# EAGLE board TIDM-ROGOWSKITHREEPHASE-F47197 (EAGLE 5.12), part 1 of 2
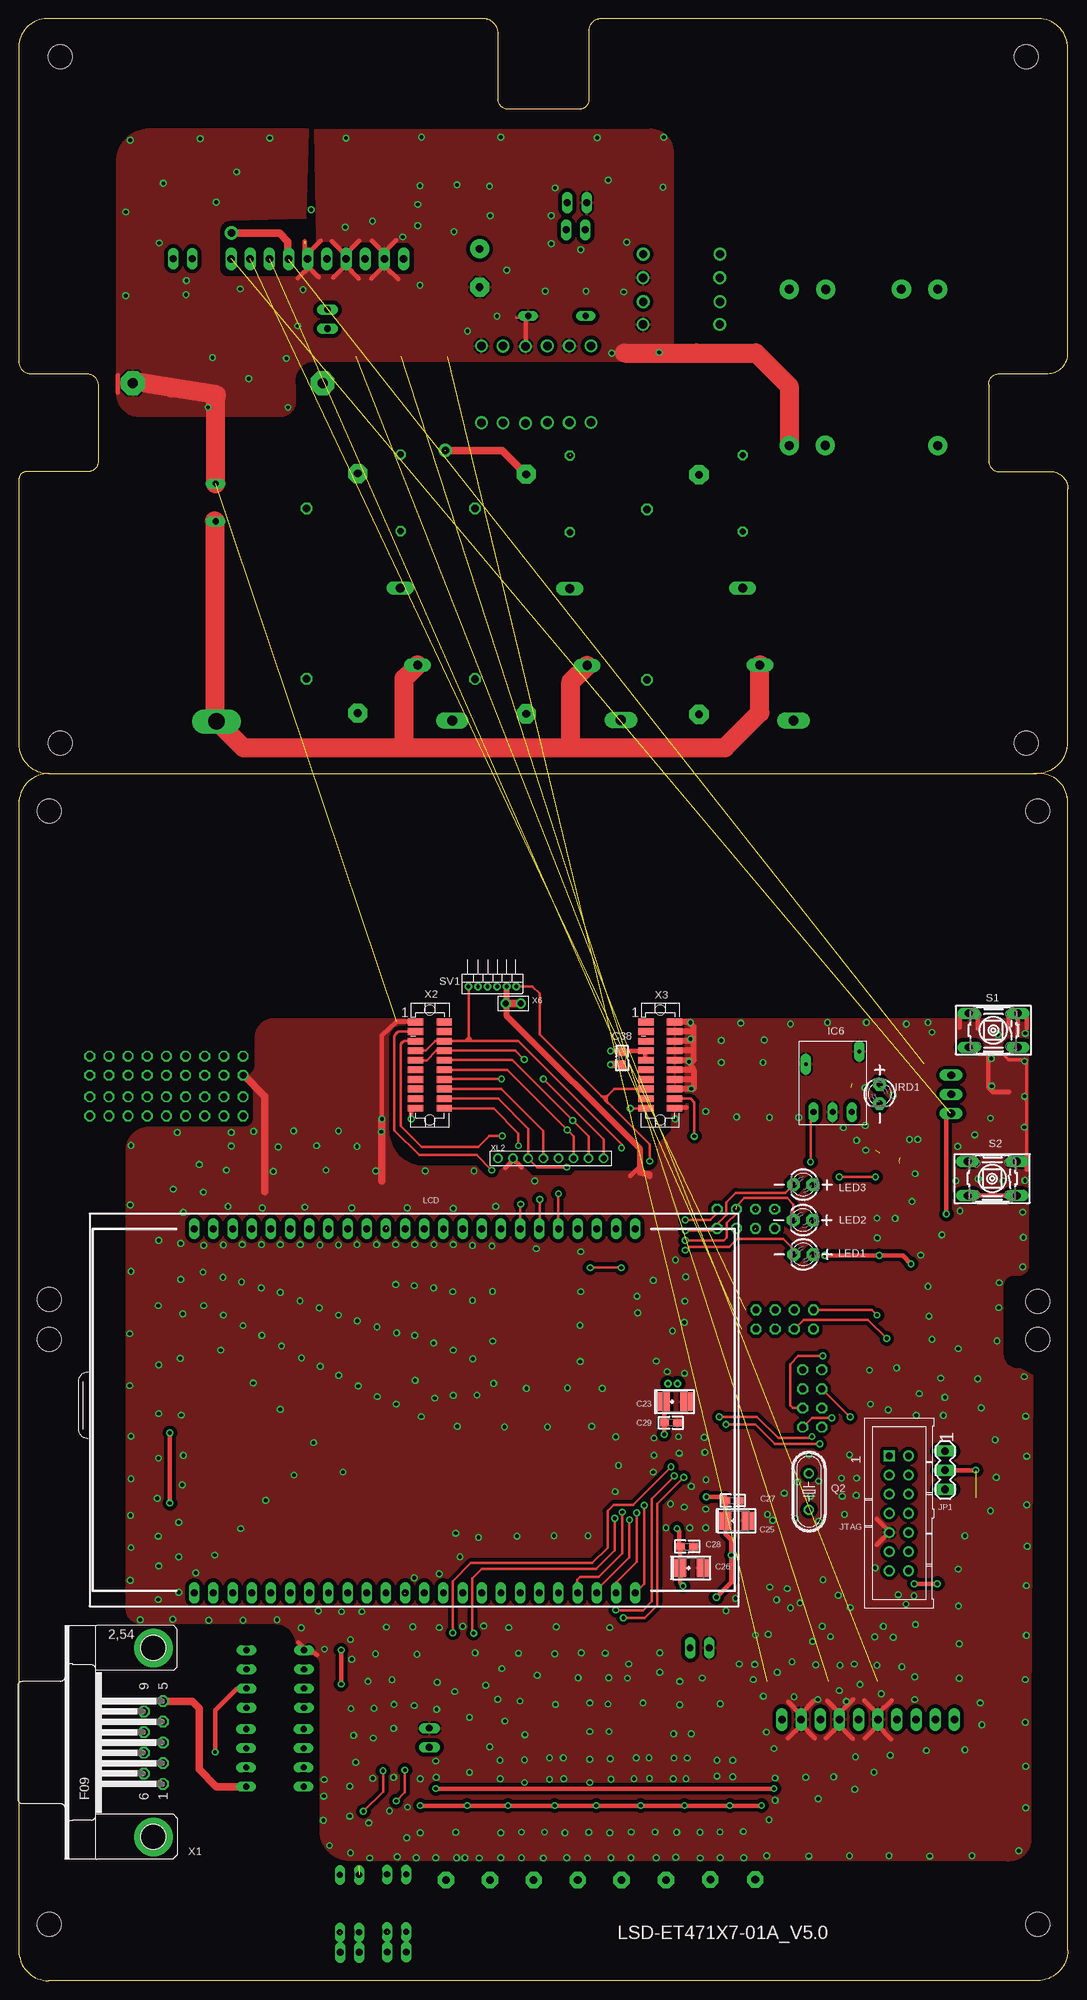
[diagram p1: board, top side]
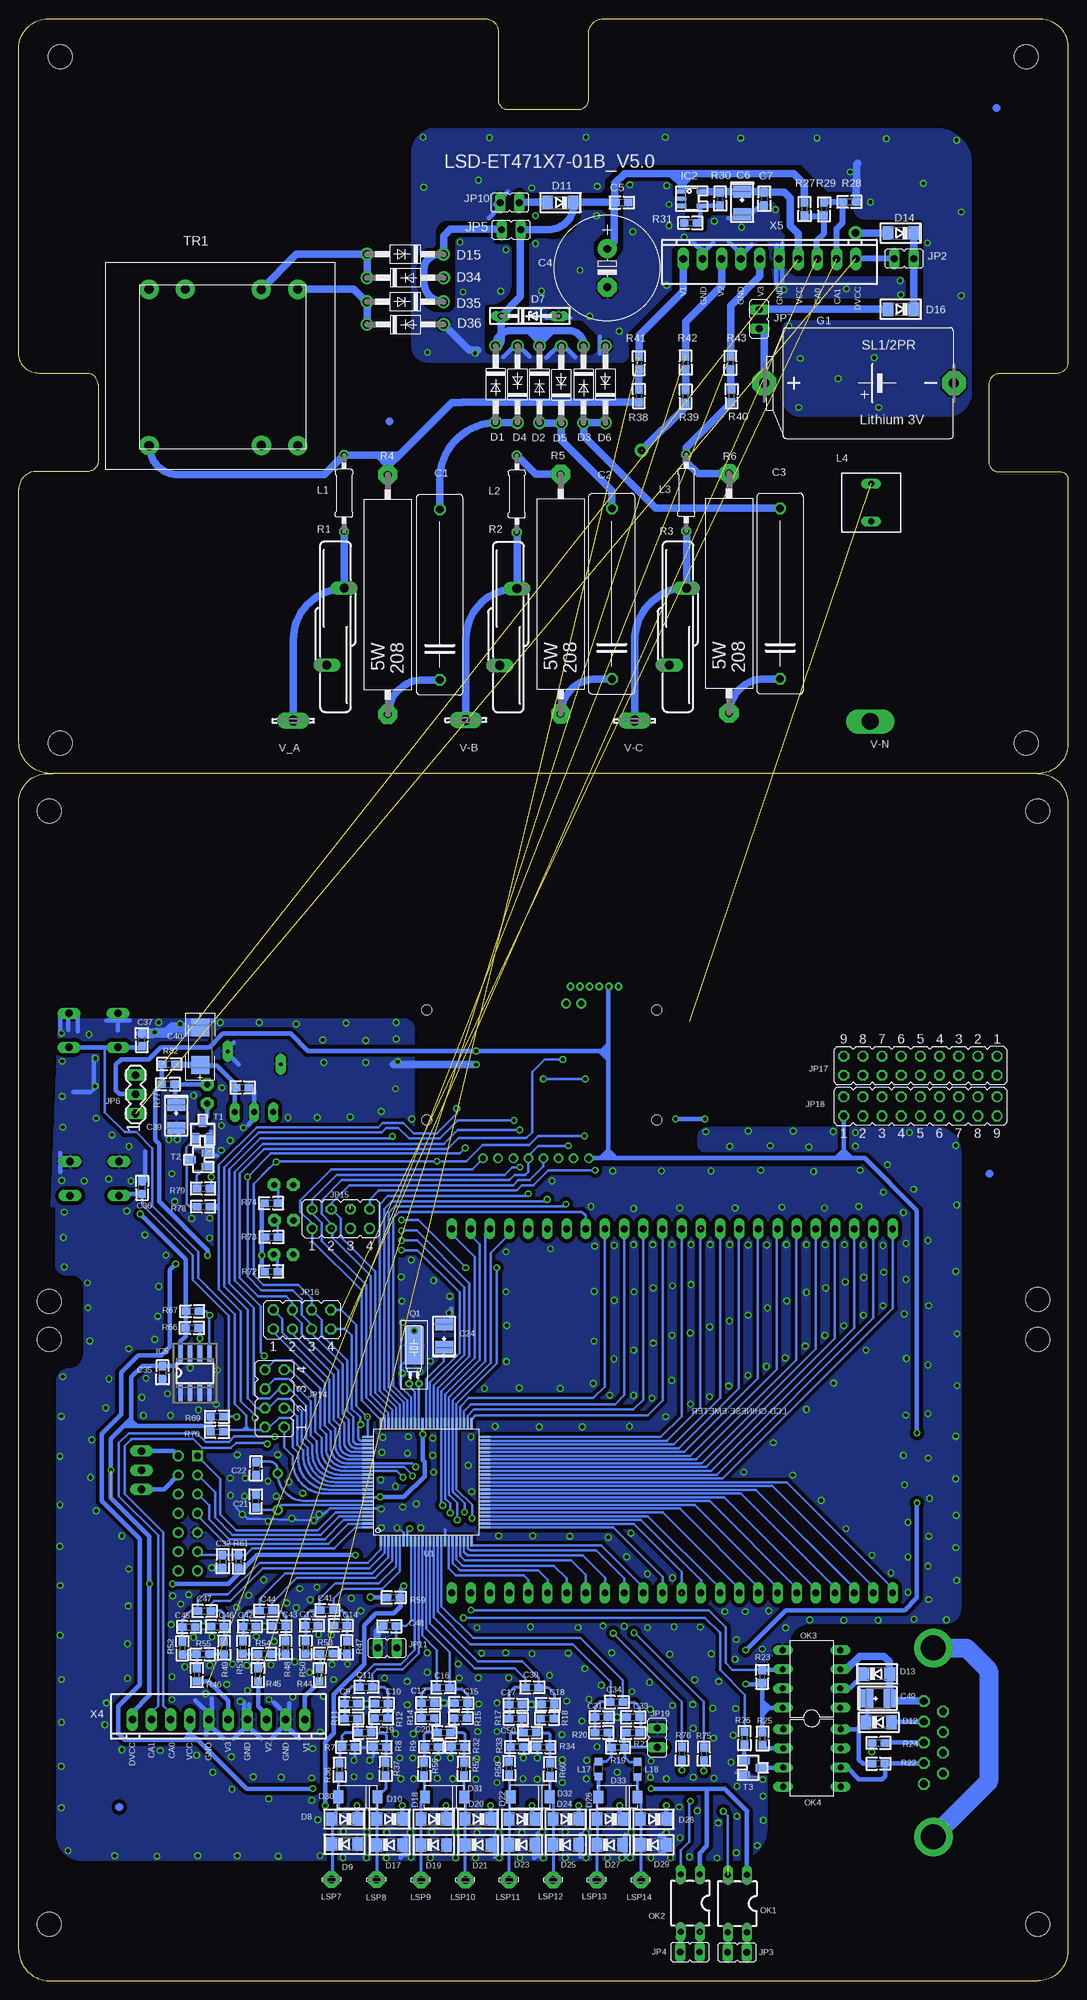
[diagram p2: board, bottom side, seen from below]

Size 139 x 260 mm. Coordinates in mm from the lower left corner, seen from the top.
Outline: 3.9,160 arc-90 0,163.9 0,198.95 arc-90 1.05,200 9.2,200 arc90 10.5,201.3 10.5,211.45 arc90 8.95,213 1.5,213 arc-90 0,214.5 0,256.3 arc-90 3.7,260 61.6,260 arc-90 63.5,258.1 63.5,249.35 arc90 64.85,248 74.25,248 arc90 75.5,249.25 75.5,258.4 arc-90 77.1,260 135.1,260 arc-90 139,256.1 139,215.65 arc-90 136.35,213 129.95,213 arc90 128.5,211.55 128.5,201.4 arc90 129.9,200 136.7,200 arc-90 139,197.7 139,164.15 arc-90 134.85,160 4,160 arc90 0,156 0,3.95 arc90 3.95,0 134.95,0 arc90 139,4.05 139,156.15 arc90 135.15,160 134.45,160
Copper layers (1*16): Top 0.035mm / dielectric 1.5mm / Bottom 0.035mm
Design rules "default": minimum track width 10mil, minimum drill 24mil, track to track 7mil, track to pad 7mil, pad to pad 7mil, via to via 8mil, smd to smd 8mil, copper to edge 15mil, drill to drill 8mil, minimum pad ring 10mil, minimum via ring 8mil, stop-mask expansion 4mil, vias tented up to drill 0mil, thermal gap 10mil
Holes 3.2 mm at 4,155 135,155 4,7.5 133.5,164 5.5,164 133.5,255 5.5,255 135,7.5 4,85 4,90.3 135,85 135,90

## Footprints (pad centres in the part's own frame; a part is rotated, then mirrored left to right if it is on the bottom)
C225-062X268 = drill 1.016 octagon: 1 -11.303,0; 2 11.303,0
E5-13 = drill 1.016 pad 2.54 round: + -2.54,0 | drill 1.016 pad 2.54 octagon: - 2.54,0
C0603 = smd 1.1 x 1: 1 -0.85,0; 2 0.85,0
SMC_B = smd 1.6 x 2.4: + -1.5,0; - 1.5,0
SMC_C = smd 2.4 x 2.4: + -2.5,0; - 2.5,0
DO41-10 = drill 1.118 round: A 5.08,0; C -5.08,0
DO34Z7 = drill 0.813 long: A -3.81,0; C 3.81,0
SOD80C = smd 1.4 x 1.8: A -1.7,0; C 1.7,0
DO-214 = smd 1.3 x 1.7: 1 0,0; 2 5.2,0
SL-150-1/2AA/PR = drill 1.321 pad 3.15 octagon: + 12.446,0; - -12.7,0
SOT23-5 = smd 0.55 x 1.2: 1 -0.95,-1.3; 2 0,-1.3; 3 0.95,-1.3; 4 0.95,1.3; 5 -0.95,1.3
SO-08 = smd 2.2 x 0.6: 1 -2.6,1.905; 2 -2.6,0.635; 3 -2.6,-0.635; 4 -2.6,-1.905; 5 2.6,-1.905; 6 2.6,-0.635; 7 2.6,0.635; 8 2.6,1.905
IR_DET1 = drill 0.8 long: 1 -2.54,-6.35; 2 0,-6.35; 3 2.54,-6.35 | drill 0.5 pad 1.422 long: 4 3.51,1.7; 5 -3.54,0
LED3MM = drill 0.8 pad 1.676 octagon: A -1.27,0; K 1.27,0
MA03-1 = drill 1.016 long: 1 -2.54,0; 2 0,0; 3 2.54,0
JP1 = drill 0.914 long: 1 0,-1.27; 2 0,1.27
JP4Q = drill 0.914 octagon: 1 -3.81,-1.27; 2 -3.81,1.27; 3 -1.27,-1.27; 4 -1.27,1.27; 5 1.27,-1.27; 6 1.27,1.27; 7 3.81,-1.27; 8 3.81,1.27
JP9Q = drill 0.914 octagon: 1 -10.16,-1.27; 2 -10.16,1.27; 3 -7.62,-1.27; 4 -7.62,1.27; 5 -5.08,-1.27; 6 -5.08,1.27; 7 -2.54,-1.27; 8 -2.54,1.27; 9 0,-1.27; 10 0,1.27; 11 2.54,-1.27; 12 2.54,1.27; 13 5.08,-1.27; 14 5.08,1.27; 15 7.62,-1.27; 16 7.62,1.27; 17 10.16,-1.27; 18 10.16,1.27
MA07-2JTAG = drill 0.9 pad 1.422 square: 1 0,0 | drill 0.9 pad 1.422 round: 2 0,2.54; 3 2.54,0; 4 2.54,2.54; 5 5.08,0; 6 5.08,2.54; 7 7.62,0; 8 7.62,2.54; 9 10.16,0; 10 10.16,2.54; 11 12.7,0; 12 12.7,2.54; 13 15.24,0; 14 15.24,2.54
0207/10 = drill 0.813 octagon: 1 -5.08,0; 2 5.08,0
SD8 = drill 0.8 long: 1 -2.5,0; 2 2.5,0
L2012C = smd 1 x 1: 1 -1,0; 2 1,0
LCD-CHINESE-EMETER = drill 0.914 long: 1 29.29,24.015; 2 26.75,24.015; 3 24.21,24.015; 4 21.67,24.015; 5 19.13,24.015; 6 16.59,24.015; 7 14.05,24.015; 8 11.51,24.015; 9 8.97,24.015; 10 6.43,24.015; 11 3.89,24.015; 12 1.35,24.015; 13 -1.19,24.015; 14 -3.73,24.015; 15 -6.27,24.015; 16 -8.81,24.015; 17 -11.35,24.015; 18 -13.89,24.015; 19 -16.43,24.015; 20 -18.97,24.015; 21 -21.51,24.015; 22 -24.05,24.015; 23 -26.59,24.015; 24 -29.13,24.015; 25 -29.13,-24.245; 26 -26.59,-24.245; 27 -24.05,-24.245; 28 -21.51,-24.245; 29 -18.97,-24.245; 30 -16.43,-24.245; 31 -13.89,-24.245; 32 -11.35,-24.245; 33 -8.81,-24.245; 34 -6.27,-24.245; 35 -3.73,-24.245; 36 -1.19,-24.245; 37 1.35,-24.245; 38 3.89,-24.245; 39 6.43,-24.245; 40 8.97,-24.245; 41 11.51,-24.245; 42 14.05,-24.245; 43 16.59,-24.245; 44 19.13,-24.245; 45 21.67,-24.245; 46 24.21,-24.245; 47 26.75,-24.245; 48 29.29,-24.245
LSP10 = drill 1.016 pad 2.159 octagon: MP 0,0
DIL04 = drill 0.813 long: 1 -3.81,1.27; 2 -3.81,-1.27; 3 3.81,-1.27; 4 3.81,1.27
DIL08 = drill 0.813 long: 1 -3.81,-3.81; 2 -1.27,-3.81; 3 1.27,-3.81; 4 3.81,-3.81; 5 3.81,3.81; 6 1.27,3.81; 7 -1.27,3.81; 8 -3.81,3.81
TC26H-1 = drill 0.5 pad 1.016 round: 1 -0.635,0; 2 0.635,0 | smd 2.54 x 5.08: 3 0,5.08
HC49/S = drill 0.813 round: 1 -2.413,0; 2 2.413,0
S20K680-1 = drill 1.2 long: 1 -1.143,-5.08; 2 1.143,5.08
KH208-8 = drill 1.016 pad 2.54 octagon: 1 -15.875,0; 2 15.875,0
R0603 = smd 1.1 x 1: 1 -0.85,0; 2 0.85,0
B3F-10XX = drill 1.016 long: 1 -3.251,2.261; 2 3.251,2.261; 3 -3.251,-2.261; 4 3.251,-2.261
MA06-1-1.27 = drill 0.5 pad 0.9 round: 1 0,0; 2 1.27,0; 3 2.54,0; 4 3.81,0; 5 5.08,0; 6 6.35,0
SOT23-BEC = smd 1 x 1.4: B -0.95,-1.1; C 0,1.1; E 0.95,-1.1
EI42-1C = drill 1.2 pad 2.54 round: 1 0,-7; 2 14.9,-6.98; 3 19.7,-7; 4 19.7,13.7; 5 14.87,13.69; 6 4.82,13.72; 7 0,13.7
PZ100 = smd 1.4 x 0.3: 1 -7.8,6; 2 -7.8,5.5; 3 -7.8,5; 4 -7.8,4.5; 5 -7.8,4; 6 -7.8,3.5; 7 -7.8,3; 8 -7.8,2.5; 9 -7.8,2; 10 -7.8,1.5; 11 -7.8,1; 12 -7.8,0.5; 13 -7.8,0; 14 -7.8,-0.5; 15 -7.8,-1; 16 -7.8,-1.5; 17 -7.8,-2; 18 -7.8,-2.5; 19 -7.8,-3; 20 -7.8,-3.5; 21 -7.8,-4; 22 -7.8,-4.5; 23 -7.8,-5; 24 -7.8,-5.5; 25 -7.8,-6; 51 7.8,-6; 52 7.8,-5.5; 53 7.8,-5; 54 7.8,-4.5; 55 7.8,-4; 56 7.8,-3.5; 57 7.8,-3; 58 7.8,-2.5; 59 7.8,-2; 60 7.8,-1.5; 61 7.8,-1; 62 7.8,-0.5; 63 7.8,0; 64 7.8,0.5; 65 7.8,1; 66 7.8,1.5; 67 7.8,2; 68 7.8,2.5; 69 7.8,3; 70 7.8,3.5; 71 7.8,4; 72 7.8,4.5; 73 7.8,5; 74 7.8,5.5; 75 7.8,6 | smd 0.3 x 1.4: 26 -6,-7.8; 27 -5.5,-7.8; 28 -5,-7.8; 29 -4.5,-7.8; 30 -4,-7.8; 31 -3.5,-7.8; 32 -3,-7.8; 33 -2.5,-7.8; 34 -2,-7.8; 35 -1.5,-7.8; 36 -1,-7.8; 37 -0.5,-7.8; 38 0,-7.8; 39 0.5,-7.8; 40 1,-7.8; 41 1.5,-7.8; 42 2,-7.8; 43 2.5,-7.8; 44 3,-7.8; 45 3.5,-7.8; 46 4,-7.8; 47 4.5,-7.8; 48 5,-7.8; 49 5.5,-7.8; 50 6,-7.8; 76 6,7.8; 77 5.5,7.8; 78 5,7.8; 79 4.5,7.8; 80 4,7.8; 81 3.5,7.8; 82 3,7.8; 83 2.5,7.8; 84 2,7.8; 85 1.5,7.8; 86 1,7.8; 87 0.5,7.8; 88 0,7.8; 89 -0.5,7.8; 90 -1,7.8; 91 -1.5,7.8; 92 -2,7.8; 93 -2.5,7.8; 94 -3,7.8; 95 -3.5,7.8; 96 -4,7.8; 97 -4.5,7.8; 98 -5,7.8; 99 -5.5,7.8; 100 -6,7.8
LSP13 = drill 1.321 pad 2.159 long: MP 0,0
LSP22 = drill 2.2 long: 1 0,0
F09HP = drill 1.016 octagon: 1 -5.486,-1.27; 2 -2.743,-1.27; 3 0,-1.27; 4 2.743,-1.27; 5 5.486,-1.27; 6 -4.115,1.27; 7 -1.372,1.27; 8 1.372,1.27; 9 4.115,1.27 | drill 3.302 pad 5.08 round: G1 -12.522,0; G2 12.522,0
TFM-110-02-SM-D-A-K = smd 2.032 x 0.889: 1 -1.27,5.08; 2 2.54,5.08; 3 -1.27,3.81; 4 2.54,3.81; 5 -1.27,2.54; 6 2.54,2.54; 7 -1.27,1.27; 8 2.54,1.27; 9 -1.27,0; 10 2.54,0; 11 -1.27,-1.27; 12 2.54,-1.27; 13 -1.27,-2.54; 14 2.54,-2.54; 15 -1.27,-3.81; 16 2.54,-3.81; 17 -1.27,-5.08; 18 2.54,-5.08; 19 -1.27,-6.35; 20 2.54,-6.35 | hole 1.359: 0.635,6.668; 0.635,-7.938
22-23-2101 = drill 1 long: 1 -11.43,0; 2 -8.89,0; 3 -6.35,0; 4 -3.81,0; 5 -1.27,0; 6 1.27,0; 7 3.81,0; 8 6.35,0; 9 8.89,0; 10 11.43,0
2POL200 = drill 0.8 round: 1 0,0; 2 2,0
MA08-1-2.0 = drill 0.75 round: 1 0,0; 2 2,0; 3 4,0; 4 6,0; 5 8,0; 6 10,0; 7 12,0; 8 14,0

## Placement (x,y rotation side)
C1  0.47uF/630V  [C225-062X268]  83.23,183.69 90 bottom
C2  [C225-062X268]  60.43,183.81 90 bottom
C3  [C225-062X268]  38.13,183.83 90 bottom
C4  2200uF  [E5-13]  61.05,226.98 270 bottom
C5  100nF  [C0603]  59.11,235.66 0 bottom
C6  22uF  [SMC_B]  43.17,235.59 270 bottom
C7  100nF  [C0603]  40.24,236.13 270 bottom
C8  100nF  [C0603]  109.37,118.37 0 bottom
C9  47pF  [C0603]  94.99,36.72 0 bottom
C10  47pF  [C0603]  90.96,36.72 0 bottom
C11  6.8nF  [C0603]  92.98,38.92 0 bottom
C12  47pF  [C0603]  84.8,36.77 0 bottom
C13  47pF  [C0603]  100.2,47.07 0 bottom
C14  47pF  [C0603]  96.37,47.07 0 bottom
C15  47pF  [C0603]  80.41,36.77 0 bottom
C16  6.8nF  [C0603]  82.78,38.87 0 bottom
C17  47pF  [C0603]  73.2,36.57 0 bottom
C18  47pF  [C0603]  68.92,36.62 0 bottom
C19  100nF  [C0603]  93.15,32.85 0 bottom
C20  100nF  [C0603]  82.65,32.9 0 bottom
C21  12pF  [C0603]  107.61,63.53 90 bottom
C22  12pF  [C0603]  107.59,67.85 270 bottom
C23  22uF  [SMC_B]  86.96,76.73 0 top
C24  22uF  [SMC_B]  82.66,85.46 90 bottom
C25  22uF  [SMC_B]  95.11,60.94 0 top
C26  22uF  [SMC_B]  89.13,54.69 0 top
C27  100nF  [C0603]  94.55,63.64 0 top
C28  100nF  [C0603]  88.52,57.54 0 top
C29  100nF  [C0603]  86.41,73.94 180 top
C30  6.8nF  [C0603]  70.99,38.87 0 bottom
C31  47pF  [C0603]  61.81,34.92 0 bottom
C32  100nF  [C0603]  111.99,55.56 270 bottom
C33  47pF  [C0603]  57.63,34.92 0 bottom
C34  15nF  [C0603]  59.8,36.92 0 bottom
C35  100nF  [C0603]  119.97,80.59 270 bottom
C36  100nF  [C0603]  122.66,105.1 90 bottom
C37  100nF  [C0603]  122.71,124.68 90 bottom
C38  100nF  [C0603]  79.93,122.25 270 top
C39  22uF  [SMC_B]  118.15,114.53 270 bottom
C40  22uF  [SMC_C]  114.97,123.83 90 bottom
C41  15nF  [C0603]  98.16,49.09 0 bottom
C42  47pF  [C0603]  108.42,46.93 0 bottom
C43  47pF  [C0603]  104.5,46.98 0 bottom
C44  15nF  [C0603]  106.25,49.02 0 bottom
C45  47pF  [C0603]  116.48,46.88 0 bottom
C46  47pF  [C0603]  112.65,46.93 0 bottom
C47  15nF  [C0603]  114.4,49 0 bottom
C48  100nF  [C0603]  89.87,46.97 180 bottom
C49  22uF  [SMC_B]  25.12,37.41 0 bottom
C50  100nF  [C0603]  71.3,32.85 0 bottom
D1  1N4007  [DO41-10]  75.82,211.59 270 bottom
D2  1N4007  [DO41-10]  70.02,211.57 270 bottom
D3  1N4007  [DO41-10]  64.17,211.55 270 bottom
D4  1N4007  [DO41-10]  72.93,211.57 90 bottom
D5  1N4007  [DO41-10]  67.13,211.49 90 bottom
D6  1N4007  [DO41-10]  61.28,211.56 90 bottom
D7  BZV10  [DO34Z7]  71.3,220.63 180 bottom
D8  1N4148  [SOD80C]  95.84,21.41 0 bottom
D9  1N4148  [SOD80C]  95.84,18.09 180 bottom
D10  1N4148  [SOD80C]  89.88,21.41 0 bottom
D11  1N4148SOD80C  [SOD80C]  67.25,235.66 0 bottom
D12  1N4148SOD80C  [SOD80C]  25.08,34.24 180 bottom
D13  1N4148SOD80C  [SOD80C]  25.31,40.64 180 bottom
D14  1N4148  [SOD80C]  22.16,231.61 0 bottom
D15  [DO41-10]  87.81,228.81 180 bottom
D16  1N4148  [SOD80C]  22.15,221.51 0 bottom
D17  1N4148  [SOD80C]  89.88,17.99 180 bottom
D18  1N4148  [SOD80C]  84.04,21.41 0 bottom
D19  1N4148  [SOD80C]  84.04,17.99 180 bottom
D20  1N4148  [SOD80C]  78.18,21.41 0 bottom
D21  1N4148  [SOD80C]  78.15,17.99 180 bottom
D22  1N4148  [SOD80C]  72.34,21.4 0 bottom
D23  1N4148  [SOD80C]  72.34,18 180 bottom
D24  1N4148  [SOD80C]  66.53,21.4 0 bottom
D25  1N4148  [SOD80C]  66.55,18 180 bottom
D26  1N4148  [SOD80C]  60.67,21.4 0 bottom
D27  1N4148  [SOD80C]  60.71,18 180 bottom
D28  1N4148  [SOD80C]  54.91,21.4 0 bottom
D29  1N4148  [SOD80C]  54.92,18 180 bottom
D30  SMAJ5.0CA  [DO-214]  91.49,24.35 180 bottom
D31  SMAJ5.0CA  [DO-214]  79.99,24.34 180 bottom
D32  SMAJ5.0CA  [DO-214]  68.64,24.36 180 bottom
D33  SMAJ5.0CA  [DO-214]  57.04,24.33 180 bottom
D34  [DO41-10]  87.79,225.69 0 bottom
D35  [DO41-10]  87.81,222.51 180 bottom
D36  [DO41-10]  87.79,219.49 0 bottom
G1  LS14250  [SL-150-1/2AA/PR]  27.8,211.72 180 bottom
IC2  TPS77001  [SOT23-5]  49.85,236.16 270 bottom
IC5  24C02CSN  [SO-08]  115.67,80.52 90 bottom
IC6  RPM7238  [IR_DET1]  107.83,121.46 0 top
IRD1  [LED3MM]  114.04,117.51 270 top
JP1  [MA03-1]  122.73,67.65 270 top
JP2  [JP1]  21.72,228.21 270 bottom
JP3  [JP1]  43.83,3.74 90 bottom
JP4  [JP1]  50.08,3.79 90 bottom
JP5  20R 3W  [JP1]  73.78,232.04 90 bottom
JP6  [MA03-1]  123.53,117.47 90 bottom
JP7  [JP1]  40.89,220.22 180 bottom
JP10  [JP1]  73.95,235.65 270 bottom
JP11  [JP1]  90.2,44.1 90 bottom
JP14  [JP4Q]  105.12,77.15 90 bottom
JP15  [JP4Q]  96.34,100.97 0 bottom
JP16  [JP4Q]  101.48,87.62 0 bottom
JP17  [JP9Q]  19.55,121.26 180 bottom
JP18  [JP9Q]  19.55,115.87 0 bottom
JP19  [JP1]  54.4,32.2 180 bottom
JTAG  [MA07-2JTAG]  115.33,69.55 270 top
L1  [0207/10]  95.92,197.12 90 bottom
L2  [0207/10]  73.02,197.03 90 bottom
L3  [0207/10]  50.57,197.19 90 bottom
L4  [SD8]  26.07,195.9 90 bottom
L17  BLM21BD121SN1D  [L2012C]  62.19,28.03 90 bottom
L18  BLM21BD121SN1D  [L2012C]  57.01,28 90 bottom
LCD  LCD-CHINESE-EMETER  [LCD-CHINESE-EMETER]  52.37,75.63 0 top
LED1  [LED3MM]  103.94,96.23 180 top
LED2  [LED3MM]  103.88,100.78 180 top
LED3  [LED3MM]  103.92,105.48 180 top
LSP7  LSP10  [LSP10]  97.56,13.4 180 bottom
LSP8  LSP10  [LSP10]  91.62,13.4 180 bottom
LSP9  LSP10  [LSP10]  85.73,13.35 180 bottom
LSP10  LSP10  [LSP10]  79.84,13.35 180 bottom
LSP11  LSP10  [LSP10]  74.05,13.35 180 bottom
LSP12  LSP10  [LSP10]  68.21,13.35 180 bottom
LSP13  LSP10  [LSP10]  62.42,13.35 180 bottom
LSP14  LSP10  [LSP10]  56.58,13.35 180 bottom
OK1  TIL191  [DIL04]  43.8,10.21 270 bottom
OK2  TIL191  [DIL04]  50.05,10.28 270 bottom
OK3  6N136  [DIL08]  33.97,39.99 90 bottom
OK4  6N136  [DIL08]  33.93,29.53 270 bottom
Q1  32.768  [TC26H-1]  86.63,79.11 0 bottom
Q2  16MHZ  [HC49/S]  104.69,64.81 270 top
R1  S20K680  [S20K680-1]  97.05,179.45 0 bottom
R2  S20K680  [S20K680-1]  74.14,179.4 0 bottom
R3  S20K680  [S20K680-1]  51.68,179.45 0 bottom
R4  470 3W  [KH208-8]  90.12,183.7 270 bottom
R5  470 3W  [KH208-8]  67.22,183.77 270 bottom
R6  470 3W  [KH208-8]  44.9,183.87 270 bottom
R7  DNP  [R0603]  95.33,30.93 180 bottom
R8  DNP  [R0603]  91.18,30.95 180 bottom
R9  DNP  [R0603]  84.33,30.97 180 bottom
R11  2.2K  [R0603]  94.99,34.75 0 bottom
R12  2.2K  [R0603]  90.99,34.8 180 bottom
R14  2.2K  [R0603]  84.8,34.8 180 bottom
R15  2.2K  [R0603]  80.47,34.8 0 bottom
R17  2.2K  [R0603]  73.19,34.72 0 bottom
R18  2.2K  [R0603]  68.99,34.73 180 bottom
R19  6.8ohm  [R0603]  59.63,30.92 0 bottom
R20  1K  [R0603]  61.8,32.88 180 bottom
R21  1K  [R0603]  57.62,32.87 0 bottom
R22  10K  [R0603]  25.12,28.75 0 bottom
R23  2K  [R0603]  40.5,40.28 90 bottom
R24  1K  [R0603]  25.08,31.5 180 bottom
R25  220R  [R0603]  40.45,32.07 270 bottom
R26  2K  [R0603]  42.85,32.12 270 bottom
R27  20K  [R0603]  34.9,234.78 270 bottom
R28  5K  [R0603]  28.93,235.75 180 bottom
R29  5K  [R0603]  32.3,234.78 90 bottom
R30  383K  [R0603]  46.08,236.15 270 bottom
R31  169K  [R0603]  50,232.95 180 bottom
R32  DNP  [R0603]  80.83,30.94 180 bottom
R33  DNP  [R0603]  72.98,30.96 180 bottom
R34  DNP  [R0603]  69.48,30.93 180 bottom
R36  100R  [R0603]  96.5,27.95 270 bottom
R37  100R  [R0603]  90.4,28.05 270 bottom
R38  330K  [R0603]  56.85,210.02 90 bottom
R39  330K  [R0603]  50.65,209.97 90 bottom
R40  330K  [R0603]  44.56,210 90 bottom
R41  330K  [R0603]  56.85,214.39 90 bottom
R42  330K  [R0603]  50.65,214.43 270 bottom
R43  330K  [R0603]  44.73,214.39 270 bottom
R44  330K  [R0603]  99.14,40.51 90 bottom
R45  330K  [R0603]  107.32,40.53 90 bottom
R46  330K  [R0603]  115.43,40.53 90 bottom
R47  1K  [R0603]  95.53,44.14 270 bottom
R48  1K  [R0603]  103.65,44.16 270 bottom
R49  1K  [R0603]  111.8,44.1 270 bottom
R50  100  [R0603]  101.01,44.16 90 bottom
R51  100  [R0603]  109.29,44.16 90 bottom
R52  100  [R0603]  117.33,44.07 90 bottom
R53  1.5K  [R0603]  98.23,43.36 180 bottom
R54  1.5K  [R0603]  106.48,43.29 180 bottom
R55  1.5K  [R0603]  114.6,43.26 180 bottom
R56  100R  [R0603]  85.3,28.05 270 bottom
R57  100R  [R0603]  80.05,28.05 270 bottom
R58  100R  [R0603]  74.05,28.15 270 bottom
R59  10 ohm  [R0603]  89.36,50.79 0 bottom
R60  100R  [R0603]  68.65,28 270 bottom
R61  47K  [R0603]  109.89,55.56 90 bottom
R66  10K  [R0603]  116.06,86.51 180 bottom
R67  10K  [R0603]  116.01,88.71 180 bottom
R69  1M  [R0603]  112.72,74.73 180 bottom
R70  1M  [R0603]  112.72,72.73 180 bottom
R72  1K  [R0603]  105.56,93.99 180 bottom
R73  1K  [R0603]  105.51,98.54 180 bottom
R74  1K  [R0603]  105.56,103.04 180 bottom
R75  1K  [R0603]  48.24,30.04 270 bottom
R76  1K  [R0603]  51.14,30.09 270 bottom
R77  470 ohm  [R0603]  119.23,118.8 180 bottom
R78  1K  [R0603]  114.56,102.59 180 bottom
R79  1K  [R0603]  114.56,104.99 180 bottom
R82  47 ohm  [R0603]  119.11,121.47 0 bottom
S1  [B3F-10XX]  129.12,125.95 180 top
S2  [B3F-10XX]  128.97,106.3 180 top
SV1  [MA06-1-1.27]  59.56,131.75 0 top
T1  BC808  [SOT23-BEC]  114.65,112.75 0 bottom
T2  BC808  [SOT23-BEC]  115.15,108.8 90 bottom
T3  MMBT2222ALT1  [SOT23-BEC]  41.77,28.21 270 bottom
TR1  EI41-1C  [EI42-1C]  121.76,210.45 0 bottom
U1  F471X7---PZ100  [PZ100]  85.03,66.06 90 bottom
V-B  LSPLSP13  [LSP13]  79.78,167.07 180 bottom
V-C  LSPLSP13  [LSP13]  57.41,166.97 180 bottom
V-N  LSPLSP22  [LSP22]  26.19,166.88 0 bottom
V_A  LSPLSP13  [LSP13]  102.64,166.97 180 bottom
X1  [F09HP]  17.83,31.57 90 top
X2  [TFM-110-02-SM-D-A-K]  53.83,121.98 0 top
X3  [TFM-110-02-SM-D-A-K]  84.35,121.98 0 top
X4  X4  [22-23-2101]  112.54,34.61 180 bottom
X5  X5  [22-23-2101]  39.54,228.19 0 bottom
X6  [2POL200]  64.5,129.5 0 top
XL2  [MA08-1-2.0]  63.49,108.97 0 top

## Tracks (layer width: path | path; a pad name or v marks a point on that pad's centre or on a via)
38KHZ  (via drill 0.5)
  Top 0.3: X3.19 83.03,115.63 83,115.6 v81,115.6 | JP14.1 105.11,74.6 v107.7,74.6
  Bottom 0.3: 112.5,102.1 112.5,91.6 109.6,88.7 109.6,76.8 107.7,74.9 v107.7,74.6 | 112.5,102.1 112.5,102.6 | 112.5,102.6 112.5,103.1 | 112.5,103.1 112.5,108.1 107.5,113.1 91.4,113.1 90.8,113.7 88.1,113.7 86.7,112.3 83.65,112.3 81,114.95 v81,115.6 | R78.1 113,102.6 | 112.5,102.6 113,102.6 | 113,102.6 112.5,103.1 | 112.5,102.1 113,102.6 | U1.91 98.46,64.56 arc90 102.7,68.8 102.7,69.55 103.85,70.7 JP14.1
+9V
  Bottom 0.254: D7.C 75.1,220.7 75.1,220.6 | 70,217.25 70.1,217.1 69.7,217.4 69.65,217.4
  Bottom 0.3: IC2.1 51.05,237.1 51.05,238.2 51.05,238.1 51.15,238.1 51.2,238.1 51.2,238.15
  Bottom 1.016: 70.05,218.7 66.15,218.7 arc90 64.15,216.7 64.15,216.61 | 70.05,218.7 73.79,218.7 arc-90 D1.C arc-90 75.85,216.7 arc-90 75.11,217.44 D7.C | 64.15,216.61 64.15,216.6 | 64.15,216.61 arc-90 D3.C | 70.05,218.7 70.05,216.68 arc-90 D2.C 70,216.67 70,217.25 71.4,218.65 | 75.1,220.6 72.55,223.15 72.55,232 JP5.1 | JP5.1 72.45,232.1 | 60.05,235.7 60.06,235.69 | 60.06,235.69 C5.1 60.05,235.67 60.05,235.7 | C4.+ 61.05,229.5 60.1,230.45 60.1,235.65 60.06,235.69 | 60.05,235.7 65.51,235.7 D11.C 65.55,235.6 arc-90 65.45,235.5 arc90 68.91,232.04 JP5.1 | 60.05,235.7 60.05,238.2 58.75,239.5 51.15,239.5 | 51.15,239.5 36.35,239.5 34.95,238.1 34.95,235.7 34.92,235.73 R27.1 | 51.15,239.5 51.15,239.3 51.15,238.1 51.15,237.5 | 51.05,238.2 49.85,239.4 | 51.2,238.15 52.4,239.35 | 69.65,217.4 68.45,218.6
ACT  (via drill 0.5, 0.5 pad 0.9)
  Top 0.3: v57.5,46.1 57.5,52.95 59.9,55.35 76,55.35 78,57.35 78,62.25 78.8,63.05 81.4,63.05 86.3,67.95 v86.4,68.1
  Bottom 0.3: v86.4,68.1 86.85,68.55 U1.83 | JP16.1 105.3,86.4 | JP16.1 | JP16.1 105.3,86 98.5,79.2 98.5,73.6 97.7,72.8 97.7,70.8 arc-90 95.46,68.56 U1.83 | U1.83 92.85,68.55 | v57.5,46.1 57.5,46.2 48.24,36.94 R75.1
AVCC  (via drill 0.5, 0.5 pad 0.9)
  Top 0.6: v53.2,23.2 v59.4,23.2 v64.8,23.2 v71,23.2 v76.5,23.2 v82.4,23.2 v88.2,23.2 v94.2,23.2 v98.4,23.2 | 87.6,54.66 87.6,54.6 | 87.6,54.66 C26.+ 87.6,54.7 | 87.6,57.51 87.6,54.7 | 87.6,54.7 87.6,54.66 | v87.2,59.9 87.5,59.6 87.5,57.6 87.58,57.6 arc-90 87.6,57.58 87.6,57.51 | 87.6,54.7 87.6,52.7 v88,52.3 | C28.1 arc-90 87.64,57.51 87.6,57.51
  Bottom 0.254: 94.14,22.84 93.98,22.84 v94.2,23.2 | 82.34,22.84 82.55,22.84 v82.4,23.2 | R59.2 88.41,50.51 | 76.48,23.12 arc-90 76.5,23.1 76.5,21.5 arc-90 76.6,21.4 76.6,20.9 | D20.C 76.48,20.92 arc90 76.5,20.9 v76.5,23.2
  Bottom 0.3: U1.8 87.53,59.6 v87.2,59.9
  Bottom 0.6: D28.C 53.21,23.09 v53.2,23.2 | 94.14,23.16 94.14,22.84 D8.C | D10.C 88.18,23.18 v88.2,23.2 | 82.34,23.16 82.34,22.84 D18.C | D20.C 76.48,23.12 | D22.C 71,21.76 v71,23.2 | D26.C 59.4,21.78 v59.4,23.2 | D24.C 64.83,23.17 v64.8,23.2 | v88,52.3 88.41,51.89 88.41,50.51 88.4,50.5 88.4,49.6 89.35,48.65 91.7,48.65 93.25,47.1 | 93.25,47.1 92,48.35 | 93.25,47.1 93.25,41.95 97.25,37.95
  Bottom 0.61: 97.25,37.95 97.25,32.8 97.3,32.75 98.4,31.65 v98.4,23.2
BT1  (1 unrouted)
  Bottom 0.3: U1.90 97.86,65.06 arc90 102,69.2 102,69.95 102.7,70.65 102.7,74.25 103.05,74.6 104.5,74.6 105.8,73.3 106.4,73.3 | C37.1 122.7,123.72 122.7,123.7 122.9,123.7 | R70.1 111.6,73 108.85,73 | JP14.2 106.75,73 108.85,73 | 108.85,73 108.85,73.05 | 108.85,73.05 108.85,73.4 | 108.85,73.4 108.85,74.9 110.4,76.45 110.4,88.3 114.05,91.95 115.2,93.1 115.2,96.55 121.3,102.65 121.3,110.3 123.45,112.45 125,112.45 127.6,115.05 127.6,123.69 | 109.25,73.05 108.9,73.4 108.9,73.1 arc-90 108.85,73.05 | 108.45,73.05 108.8,73.4 108.85,73.4 | 125.85,123.7 125.86,123.7 S1.2
  Bottom 0.6: C37.1 122.71,123.71 122.7,123.7 122.71,123.69 S1.2 127.6,123.69 132.19,123.69 132.2,123.7 132.21,123.69 S1.1
BT2  (via drill 0.5)
  Top 0.3: JP14.6 110.11,74.7 v110.15,74.7
  Top 0.6: 125.72,104.08 125.7,104.1 | S2.2 125.72,104.08 | S2.1 125.76,104.04 125.72,104.08
  Bottom 0.3: C36.1 122.66,102.81 115.95,96.1 115.95,92.85 111.2,88.1 111.2,74.75 111.7,74.75 | 111.85,74.75 arc-90 R69.1 111.85,74.75 | 111.7,74.75 111.85,74.75 | v110.15,74.7 110.2,74.75 111.7,74.75 | U1.86 96.51,67.06 arc90 99.5,70.05 99.5,71.45 100.3,72.25 100.3,76.8 103.25,79.75 105.1,79.75 106.4,78.45 106.39,78.44 JP14.6
  Bottom 0.61: S2.2 125.74,104.04 125.75,104.05 125.55,104.25 C36.1
CA0  (via drill 0.5, 0.5 pad 0.9)  (1 unrouted)
  Top 0.3: v93.7,73.7 97.6,73.7 100.15,71.15 v106.1,71.15
  Bottom 0.3: U1.77 93.66,71.56 arc90 94,71.9 94,73.3 93.8,73.5 | 93.8,73.5 93.8,74.7 94.9,75.8 94.9,85.5 95.8,86.4 97.62,86.4 JP16.7 | v93.7,73.7 93.7,73.6 93.8,73.5 | 118.89,35.41 118.9,35.4 | 118.89,35.41 X4.8 | 118.89,35.41 118.85,35.45 118.85,35.4 119.9,36.45 119.9,59.4 125,64.5 125,70.9 124.2,71.7 124.1,71.8 115.9,71.8 114.7,70.6 110.9,70.6 110.2,71.3 106.25,71.3 v106.1,71.15
  Bottom 0.813: X5.8 33.25,228.2 33.25,230.6 32.3,231.55 R29.1 32.33,233.8 34.87,233.8 R27.2
CA1  (via drill 0.5)  (2 unrouted)
  Top 0.3: v92.8,74.7 97.8,74.7 100.6,71.9 104.9,71.9 v105.1,72.1
  Bottom 0.3: 92.83,74.73 94.3,76.2 94.3,86.9 96.3,88.9 97.6,88.9 97.61,88.89 JP16.8 | U1.76 92.8,72.09 v92.8,74.7 | v105.1,72.1 110.45,72.1 111.15,71.4 114.25,71.4 115.4,72.55 124.45,72.55 125.75,71.25 125.75,64.2 120.55,59 120.55,36.4 121.4,35.55
  Bottom 0.305: X4.9 121.43,34.58 121.4,34.55 121.4,35.55
  Bottom 0.813: 29.88,235.73 R28.2 | 29.88,235.73 32.27,235.73 32.3,235.7 R29.2 | 29.88,235.73 29.85,235.7 29.85,233 30.65,232.2 X5.9
COM0  (via drill 0.5 pad 0.9)
  Top 0.254: 74,53.1 74,53
  Top 0.3: LCD.45 74.04,51.94 74,51.8 74,53 | 74,53.1 74.4,53.5 76.85,53.5 79.95,56.6 v79.95,62.1
  Bottom 0.3: LCD.4 74,99.6 74.1,99.5 74.1,98.85 76.5,96.45 76.5,81.9 81.53,76.87 U1.56 81.53,64.83 79.95,63.25 | 79.95,63.25 81.5,64.8 | 79.95,63.25 v79.95,62.1
COM1  (via drill 0.5 pad 0.9)
  Top 0.3: LCD.46 76.58,51.78 80.9,56.1 v80.9,61.05
  Bottom 0.3: LCD.3 76.58,99.62 77.2,99 77.2,82.1 82.03,77.27 U1.57 82.03,64.43 | v80.9,61.05 80.9,63.3 82.03,64.43 | 82.03,64.43 81.9,64.3
COM2  (via drill 0.5 pad 0.9)
  Top 0.3: LCD.47 79.12,52.77 81.85,55.5 v81.85,62
  Bottom 0.3: 79.12,99.68 79.1,99.7 | 79.12,99.68 LCD.2 | 79.12,99.68 79.2,99.6 79.2,98.9 77.9,97.6 77.9,82.3 82.53,77.67 U1.58 82.53,63.93 81.85,63.25 | 81.85,63.25 82.53,63.88 82.52,63.88 82.5,63.9 | 81.85,63.25 v81.85,62
COM3  (via drill 0.5 pad 0.9)
  Top 0.3: LCD.48 81.69,51.39 81.9,51.6 81.75,51.5 82.85,52.6 v82.85,63
  Bottom 0.3: LCD.1 81.7,99.6 81.7,99 78.6,95.9 78.6,82.5 83.03,78.07 U1.59 83.03,62.98 82.85,62.8 v82.85,63
CS  (via drill 0.5 pad 0.9)
  Top 0.3: X2.14 56.4,119.47 56.4,119.5 v63.95,119.5 | XL2.8 77.49,111.51 v69.5,119.5
  Bottom 0.3: U1.75 91.03,74.33 93.6,76.9 93.6,91.45 100.15,98 JP15.1 100.15,100.35 101.7,101.9 101.7,103.4 97.6,107.5 78.96,107.5 XL2.8 | v69.5,119.5 v63.95,119.5
DVCC  (via drill 0.5, 0.6)  (2 unrouted)
  Top 0.6: 93.6,64.1 C25.+ 93.6,59.2 94.4,58.4 v94.4,56.4 94.4,52.8 v92.41,50.81 | 93.6,64.1 C27.1 | 85.5,73.98 C29.2 | C23.+ 85.5,76.59 85.5,73.98 | v85.5,72.4 85.5,73.98 | 93.6,64.1 v91.1,64.1 91.1,64.2 | v118.65,52.6 v121.7,52.6 | JP1.2 v126.8,67.65
  Top 0.61: JP6.1 123.5,114.95 122.9,114.35 v122.9,101.6
  Bottom 0.254: v91.1,64.1 arc90 v91.11,64.09 arc-90 91.14,64.06
  Bottom 0.3: 91.14,64.06 U1.92 | U1.64 85.53,72.3 85.5,72.3 | IC5.8 117.58,82.1 117.6,82.1 | 124.1,74.55 124.1,74.5 124.15,74.45 | 126.8,64
  Bottom 0.406: 23.5,228.21 23.5,228.19
  Bottom 0.6: R70.2 R69.2 | R70.2 113.6,72.7 | C35.1 118.26,81.44 117.6,82.1 117.6,84.7 116.9,85.4 116.9,85.8 116.91,85.81 R66.2 116.91,88.59 | 116.91,88.59 116.96,88.54 R67.2 | 116.91,88.59 116.9,88.6 | v85.5,72.4 85.5,72.3 85.5,69 85.25,68.75 | 125.05,73.5 123.05,73.5 113.6,73.5 R70.2 | v94.4,56.4 107.4,56.4 | 111.9,52.6 v118.65,52.6 | 116.91,88.59 116.91,95.61 v122.9,101.6 | v121.7,52.6 121.7,58.85 126.8,63.95 126.8,64 | 126.8,64 | 126.8,64 126.8,71.8 | 126.8,71.8 126.75,71.85 | 126.8,71.8 124.15,74.45 | R59.1 92.38,50.78 v92.41,50.81 | X4.10 123.98,35.45 124,35.45 124,35.5 121.7,37.8 121.7,39.1
  Bottom 0.61: C35.1 119.97,81.48 119.95,81.5 122.6,81.5 124.1,80 124.1,74.55 | 124.1,74.55 124.55,73.5 | v121.7,52.6 121.7,39.1 | 110.01,54.71 110.1,54.8 109,54.8 108.86,54.94 | 110.01,54.71 R61.1 | 107.4,56.4 108.86,54.94 | 123.05,73.5 123.4,73.5 124.1,74.2 124.1,74.55 | 108.86,54.94 110.25,53.55 | 111.9,52.6 111.25,52.6 110.01,53.84 110.01,54.71 | 91.15,64.15 v91.1,64.1 88,64.1 85.25,66.85 85.25,68.75
  Bottom 0.813: JP2.1 23.5,228.21 | 23.5,228.19 X5.10
GDO0  (via drill 0.5 pad 0.9)
  Top 0.3: X2.10 56.58,121.98 56.6,122 56.35,122 | 56.35,122 56.2,122 | X2.10 56.35,122 | X2.10 56.8,121.98 56.8,122 65.4,122 73.35,114.05 73.4,114.05 v73.4,114 75.5,111.9 75.5,108.95 XL2.7
  Bottom 0.3: 106.4,75.9 JP14.4 | JP14.4 106.08,75.88 106,75.8 104.7,77.1 103.1,77.1 101.5,75.5 101.5,75.4 101.5,71.4 100.7,70.6 100.7,69.7 arc-90 97.06,66.06 U1.88 | 111.8,107.8 111.8,92 108.7,88.9 108.7,77.15 107.4,75.85 106.4,75.85 106.4,75.9 | 73.35,114.05 v73.4,114 80.85,114 83.25,111.6 87.3,111.6 88.7,113 90.3,113 90.9,112.4 107.2,112.4 111.8,107.8 | 111.8,107.8 111.8,107.7 | 106.4,75.9 JP14.4
GDO1  (via drill 0.5)
  Top 0.3: X3.18 89,116.9 89.5,116.4 v89.5,111.9
  Bottom 0.3: JP14.5 103.42,78.42 103.4,78.4 | 103.4,78.4 103.8,78.4 | 103.1,78.4 103.4,78.4 | 103.1,78.4 100.9,76.2 100.9,71.8 100.1,71 100.1,69.8 arc-90 96.86,66.56 U1.87 | v89.5,111.9 89.8,111.6 107,111.6 111.1,107.5 111.1,92.4 107.85,89.15 107.85,88.4 107.85,77.7 107.3,77.15 105.75,77.15 104.5,78.4 103.1,78.4
GDO2  (via drill 0.5)
  Top 0.3: X2.12 64.7,120.7 v72.65,112.75 | XL2.6 73.5,108.95 73.5,111.9 72.7,112.7 | v72.65,112.75 72.7,112.7 | JP14.3 102.57,75.88 102.2,76.25 102.2,81.7 103.3,82.8 v106.5,82.8 106.55,82.8 | v72.65,112.75 72.7,112.75 72.7,112.7
  Bottom 0.3: 72.75,112.75 80.85,112.75 82.7,110.9 106.7,110.9 110.4,107.2 110.4,92.8 106.95,89.35 106.95,83.25 v106.5,82.8 | 72.75,112.75 72.65,112.85 | U1.89 97.31,65.56 arc90 101.35,69.6 101.35,70.25 102.1,71 102.1,74.75 103.25,75.9 103.85,75.9 JP14.3 | 72.75,112.75 v72.65,112.75
GND  (via drill 0.5, 0.5 pad 0.9)  (5 unrouted)
  Top 0.254: 67.13,220.28 65.9,220.4 67.3,220.3 | 67.3,220.3 67.3,220.4 | 67.3,220.3 67.4,220.3 67.4,220.4
  Top 0.3: 20.25,211.12 20.35,211.22 20.35,211.7 20.25,211.6 20.25,211.15
  Top 0.406: X2.19 52.6,115.7 | 38.62,43.46 38.6,43.46 38.6,43.55 38.32,43.55 | 133.56,109.38 133.56,122 131.15,122 130.1,123.05
  Top 0.6: X2.19 52.63,115.63 arc90 52.7,115.7 52,115.7 v52,114.2 | v48.1,114.2 48.1,125.25 50.1,127.1 52.7,127.1 52.66,127.06 X2.1 | 15.35,211.9 15.17,211.72 G1.- | D7.A 67.13,220.28 D5.A | S1.3 132.37,125.5 132.3,125.5 | 113.86,33.93 112.05,32.13 | 115.62,32 113.82,33.81 | 108.72,33.86 110.52,32.05 | 108.75,33.92 106.94,32.12 | 103.68,33.95 105.48,32.14 | 103.71,33.93 101.9,32.13 | 105.35,37.07 103.64,35.37 | 112.03,37.15 113.73,35.44 | 115.66,37.18 113.95,35.48 | 13.07,210.49 13.07,212.8 | 13.19,211.73 15.5,211.73 | 115.37,59.5 113.67,61.21 | 113.69,57.77 115.4,59.47 | 110.56,37.28 108.85,35.58 | 101.92,36.96 103.62,35.25 | 38.32,43.55 37.02,44.86 | 39.52,43.15 39.4,43.2 39.14,43.46 38.62,43.46 | 65.32,109.06 66.62,107.75 | 65.75,109.02 64.44,107.72 | 86.68,115.75 88.48,115.74 | 133.55,107.48 133.56,109.38 | 133.55,126.28 133.55,128.15 133.5,128.2 133.56,128.18 | 124.64,126.32 124.65,128.22 | 127.04,126.22 127.05,128.12 | 131.14,126.22 131.15,128.12 | 128.45,118.38 128.46,122.78 | 131.22,117.75 129.05,117.75 128.5,118.3 128.5,118.4 | 81.04,106.62 82.35,107.92 | 45.06,225.57 43.35,227.27 | 41.67,225.69 43.37,227.4 | 46.72,225.59 48.42,227.3 | 50.25,225.48 48.54,227.18 | 48.28,228.95 49.98,230.66 | 46.75,230.57 48.46,228.87 | 43.37,228.89 45.07,230.6 | 41.44,230.53 43.15,228.83 | 38.28,228.9 39.98,230.61 | 37.88,228.25 37.88,230.51 | 36.98,225.6 38.68,227.31 | 38,227.47 39.71,225.77 | 107.12,37.06 108.82,35.35
  Top 0.813: X3.2 88.74,127.06 89.4,126.4 89.4,125.8 | 89.4,119.4 89.4,118.2 89.3,118.2 arc-90 89.27,118.17 X3.16 | 89.4,120.7 89.4,119.4 | 89.4,120.7 v88.8,121.8 89.4,122 | 89.4,122 89.4,123.2 | 89.4,123.2 89.4,124.5 | 89.4,124.5 89.4,125.8 | 86.9,115.6 X3.20 | 89.4,119.4 89.3,119.4 arc90 89.26,119.44 X3.14 | 89.4,120.7 89.3,120.7 arc90 89.29,120.71 X3.12 | X3.10 89.38,121.98 arc90 89.4,122 | 89.4,123.2 89.3,123.2 arc90 89.25,123.25 X3.8 | 89.4,124.5 89.3,124.5 arc90 89.28,124.52 X3.6 | 89.4,125.8 89.3,125.8 arc-90 89.29,125.79 X3.4 | 64.64,129.36 SV1.5 | 82.3,107.8 82.3,107.1 | 82.3,107.8 82.3,110.2 64.64,127.86 64.64,129.36 | 64.64,129.36 X6.1 | 83.58,106.64 83.58,106.82 arc90 83.5,106.9 83.2,106.9 arc-90 82.3,107.8
  Top 1.016: v48.1,114.2 48.1,106 | JP17.18 29.8,120 32.6,117.2 32.6,104.6 | v78.4,121.4 C38.2 | X6.1 X6.2
  Top 2.54: L4.2 26.07,209.8 26.15,209.8 26.17,210.18 20.25,211.12 15.35,211.9 | TR1.3 102.05,211.35 97.7,215.7 89.81,215.69 89.76,215.7 80.25,215.7
  Bottom 0.254: 40.24,235.3 40.2,235.3 | C7.2 40.24,235.3 | 40.59,235.53 40.59,235.3 40.24,235.3 | v75.35,16.25 76.1,16.3 75.92,16.3 arc-90 75.73,16.49 | 75.93,16.89 arc90 75.92,16.9 75.9,16.9 75.9,19.03 arc90 75.83,19.1 | C9.2 94.15,36.75 93.97,36.72
  Bottom 0.3: U1.18 82.53,59.73 82.6,59.8 | 87.3,82.6 88.4,81.5 88.4,78.7 87.03,77.33 U1.67 | 110.1,62.6 108.69,61.19 107.09,61.19 99.7,61 98.3,62.1 97.84,62.56 U1.95 91.26,62.56 91,62.3 | U1.7 88.03,59.33 88.7,60 | C39.- 118.6,112.93 v119.1,111.5 | 44.01,27.53 43.1,27.53 | 42.61,27.03 40.9,27.03 | 65.93,220.4 65.95,220.4 | 111.61,123.23 111.6,123.24 111.6,123.25 111.63,123.25 111.67,123.21 | 113.41,54.71 113.4,54.7 v113.45,54.7
  Bottom 0.406: 60.68,34.92 60.66,34.9 v59.7,34.9 | C45.2 115.58,46.88 115.55,46.85 115.47,46.93 C46.1 | R53.1 95.56,43.36 | R48.2 103.7,43.35 103.76,43.29 R54.1 | R55.1 R49.2 | 42.6,27.03 42.6,27 | 42.6,27.03 42.61,27.03 | T3.E 42.6,27.26 42.6,27.03 | 54.05,17.2 54.1,17.2 54.1,16.79 53.53,16.79 | 54.05,17.3 54,17.3 54,18 D29.A | 83.45,30.94 R32.2 81.68,29.67 v81.8,29.55 | 83.45,30.94 R9.1 | v70.3,29.55 70.33,29.58 R34.2 70.36,30.96 R33.1 72.13,29.57 v72.15,29.55 | 83.45,30.94 83.45,29.6 v83.5,29.55 | v92.5,29.2 92.03,29.67 R8.2 94.46,30.95 R7.1 94.48,29.32 v94.6,29.2
  Bottom 0.6: v48.1,114.2 v52,114.2 | D23.A 70.7,17.94 70.7,16.2 | 108.42,118.52 108.5,118.6 | 108.42,118.52 C8.2 | IC6.2 107.83,117.93 108.42,118.52 | 125.87,125.9 S1.4 | 132.47,126 132.47,128.31 | 129.07,118.1 129.07,122.51 | 129.49,117.77 131.8,117.77 | 113.29,127.27 116.7,127.27 | 117.83,111.49 117.83,113.1 | 108.61,113.43 107.85,114.28 | 114.07,109.7 114.07,112.01 | 111.61,123.23 110.5,124.33 | 109.87,121.4 111.67,123.21 | 124.29,127.27 127.4,127.27 | 122.23,106.09 122.23,109.9 | 81.73,86.79 81.73,89.1 | 53.53,16.79 53.53,19.6 | 58.63,19.3 58.63,16.39 | 64.53,19.4 64.53,16.39 | 70.23,19.5 70.23,16.49 | 75.93,16.89 75.93,19.2 | 75.73,16.49 75.73,19.03 75.8,19.1 75.83,19.1 | 87.73,19.2 87.73,16.69 88.01,16.69 arc-90 88.39,16.31 | 103.7,33.92 101.89,32.12 | 103.68,33.95 105.48,32.14 | 108.73,33.85 110.53,32.04 | 108.71,33.83 106.9,32.03 | 113.76,33.93 111.95,32.13 | 115.61,37.18 113.8,35.38 | 71.33,215.2 73.03,216.91 | 73.1,216.87 74.81,215.17 | 67.4,216.77 69.11,215.07 | 65.27,215.19 66.97,216.9 | 62.03,215.6 62.03,217.91 | 41.9,230.07 43.61,228.37 | 43.27,228.79 44.97,230.5 | 48.07,228.79 49.77,230.5 | 46.99,230.33 48.7,228.63 | 38.67,224.89 38.67,230 | 37.87,225.09 37.87,230.2 | 75.91,235.37 74.2,237.07 | 75,235.27 76.71,233.57 | 103.2,36.77 103.19,34.67 | 109.15,36.97 109.19,35.37 | 113.41,37.43 113.4,35.43 | 133.5,107.17 133.49,109.67 | 133.5,125.67 133.49,128.17 | 131.2,125.77 131.19,128.27 | 40.59,235.53 42.3,233.83 | 43.43,233.6 45.03,233.61 | 113.5,110.07 113.49,112.57 | 112.73,109.39 114.43,109.4 | 54.06,19.28 54.05,17.3 54.05,17.2 54.05,16.98 | 115.2,125.43 117.01,125.43 | 65.93,220.4 69.1,220.4 69.03,220.41 | 105.21,36.88 103.4,35.08 | 108.45,36.62 108.49,34.52
  Bottom 0.6: 114.2,34.67 114.19,32.57
  Bottom 0.61: C9.2 93.97,36.72 92.97,36.72 v92.95,36.7 | R47.2 95.53,43.33 95.56,43.36
  Bottom 1.016: 78.21,216.06 78.25,216.1 79.32,216.1 D36.A | R28.1 27.98,240.77 27.85,240.9 | v78.4,121.4 89.4,121.4 v88.8,121.8 | C31.2 60.72,34.92 60.7,34.9 60.68,34.92 C33.1 | C18.1 72.08,36.62 72.13,36.57 C17.2 72.08,36.57 72.05,36.6 v71.1,36.6 | C15.1 83.73,36.77 83.75,36.75 83.77,36.77 C12.2 83.83,36.77 83.8,36.8 v82.7,36.8 | 93.97,36.72 C10.1 | C48.2 91.5,46.2 91.5,44.1 JP11.2 | C32.2 113.41,54.71
  Bottom 1.422: C37.2 119.37,125.63 118.7,126.3 115,126.3 C40.-
  other vias: 14.7,85.75 26.75,83.55 129.9,92.5 85.45,244.3 76.65,244.25 63.85,244.3 53.35,244.3 43.35,244.2 33.25,244.2 24.05,244.1 14.75,243.9 14.15,234.4 14.15,223.3 85.35,237.7 84.85,215.8 78.55,215.7 80.55,230.4 74.45,229.4 80.15,223.8 70.55,230.2 70.55,233.9 62.45,233.9 53.15,237.9 58.05,238 64.65,226.7 53.15,224.7 69.75,223.9 52.85,235.4 38.75,234.7 52.85,232.6 26.15,235.7 22.2,225.3 37.65,224.1 35.65,208.5 36.95,219.3 25.65,215.1 25.05,208.5 75.15,223.9 63.35,220.6 57.65,231.8 59.45,218.6 35.45,215 19.15,238.2 43.25,232.4 62.35,237.8 71.05,237.6 78.1,238.6 50.85,231.1 28.85,239.7 129.6,84.8 122.15,79.85 127.05,79.75 133.55,63.05 133.5,45.75 115.45,29.85 132.5,17.2 115.3,16.55 110.05,16.55 105.9,24.1 99.1,16.55 100.2,23.9 110.75,25.35 120.7,16.5 133.35,39.9 125.35,30.6 127.4,36.8 133.5,52.35 124.6,40.05 105.15,44.95 97.6,45.8 113.7,41.8 106.45,46.95 114.55,46.95 80.8,41.95 74.1,40.15 61.85,39.15 66.2,43.4 71,43.3 67,26.25 63.8,26.75 55.3,26.95 47.25,43.3 78.3,46.8 64.9,46.8 46.25,39.65 46.9,26.8 87.55,36.55 53.2,26.75 55.45,39.55 40.35,21.25 41.15,17.9 51.5,23 53.2,19.6 42.95,67.4 31.05,79.2 21.8,69.6 21.45,92.95 27.5,107.4 60.3,107.3 53.85,107.3 51.45,102.4 37.9,102.5 40.45,26.65 14.75,102.8 20.45,104.9 14.7,78.85 34.65,75.7 14.85,94 88.15,62.75 125.35,58.95 124.5,49.65 18.55,98.1 18.45,89.45 18.55,81.6 36.4,112.6 21.8,101.8 63.2,102.6 40.7,107.4 14.85,110.7 99.4,21.3 92.95,16.3 96.05,16.3 90.3,16.25 87.05,16.35 84.45,16.3 81.1,16.3 78.45,16.3 78.3,19.6 72.35,19.6 69.5,16.25 46.5,16.25 57.9,19.65 58,16.3 63.85,19.6 63.85,16.3 66.6,19.7 66.6,16.3 78.2,33 67,29.25 89.1,32.7 71.2,46.9 133.1,98.5 133,101.85 84.45,82.1 74.45,91.3 87.5,69.9 111,111.35 121,125.7 129.7,125.4 118,111.5 117.6,126.8 77.7,43.4 89,127 89,124.8 102.25,126.8 98.75,124.65 93.05,124.6 86.95,114.2 103.35,114.4 91,115.2 89.1,118.2 93.05,121.7 124.4,110.55 112.2,110.05 109.25,113.05 112.3,127 124.7,102 121,85 119.5,96.15 133,94.6 133.2,80.05 124.45,54.55 133.2,113.1 116.3,81.2 112.7,80.9 112.85,76.4 115.2,75.65 122.7,77.3 122.5,74.9 118.9,74.9 119.3,77.8 101.4,64.6 104.7,69.7 104.9,64.2 106,66.2 109,66.6 110.05,69.7 110.95,64.3 109.1,64.2 111,66.6 109.4,61.8 99.2,61.8 99.9,61 106,60.9 103.2,66.1 91,62.5 88.9,60 91,60 90.9,70 87.4,72.1 90.8,72 91.05,66.35 88.35,93.25 81.9,90.7 82,88.5 88.15,87.25 88.2,80.5 85.9,80.7 86.6,86.1 62.7,97.35 74.45,96.6 77.3,78.5 62.9,79.15 62.75,91.35 74.35,86.85 62.8,84.75 28.15,112.4 21,112.4 28.15,110.6 21.4,82.45 21.45,97.7 59.1,16.3 61,16.25 48.7,46.85 52.2,46.9 75.65,26.25 29.35,224.2 30.45,212.3 18.6,230.3 46.85,233.2 43.85,25.75 87.55,39.65 100.05,30.75 100.2,26.85 107.95,27 86.7,26.75 104.25,26.95 94.95,50.65 93.7,49 97.5,41.9 95.45,41.95 99.3,45.9 99.5,52.15 101.8,51.95 102.25,49.4 102.45,42.25 102.7,37.6 105.6,41.85 106.55,53.1 110.15,49.45 110.7,41.95 113.4,45.55 116.5,51.15 118.6,51 118.7,40.25 118.8,47.2 118.7,37.25 117,41.6 113.3,27.6 104.65,16.5 126.3,16.55 133.4,28.4 127.6,33.9 129.5,66.7 70.3,26.7 72.2,26.75 83.55,26.8 81.5,26.75 94.6,27 92.5,27.1 55.25,29.1 67.05,32.6 66.4,37.05 78.45,26.7 78.35,29.4 80.65,40.1 84.9,43.45 90.55,40.1 84.9,40.85 22.15,223.45 21.65,65.7 36.45,67 21.2,56.15 23.45,54.05 21.2,60.75 29.4,59.9 42.35,112.6 49.7,36.6 72.6,16.3 69.65,19.7 75.5,19.65 84.3,19.7 90.25,19.65 88.4,26.75 108.55,51.05 107.55,45.6 117.55,49.9 98.65,37.7 99.05,32.95 97.3,39.9 24.45,104.5 32.25,102.4 44.1,102.4 68.35,106 21.7,88.35 21.5,74.95 48,112.5 113.7,101.05 113.75,98.45 116.1,101 118.35,103.25 118.75,106.95 40.4,24.45 88.25,90.05 84.05,92.8 87,95.5 110.85,29.65 100.5,40.85 108.8,41.8 109.65,37 114.25,38 133.25,121.85 133.35,125.55 128.75,114.3 126.65,112.1 127.1,106.25 124.15,106 133.3,106.05 130.35,106 122.3,98.85 127.5,75.9 129.35,71.65 133.55,69.5 128.75,62.25 18.45,58.9 18.55,54.95 21.2,51.45 14.85,57.4 18.35,63.9 14.85,72.15 18.55,75.15 57.55,102.35 25.95,56.4 102.85,61.25 62.4,31 68.7,40.45 78.05,36.65 78.15,40.15 86.8,29.5 88.55,29.5 86.75,32.7 74.5,43.45 64.4,34.4 60.45,43.45 49.45,39.85 75.65,29.35 75.65,36.8 75.65,33 31.1,112.55 34.35,110.5 79,64.8 75.9,73.45 70.05,73.4 58.1,73.45 47.3,107.3 14.85,66.5 33.7,107.25 44.8,110.55 14.8,61.65 39.45,110.65 14.75,53.05 27.7,102.6 16.1,47.8 18.45,50.5 20.4,47.9 25.15,47.75 29.7,47.75 34.2,47.8 37.4,46.75 40.5,43.95 39.65,49 45.45,48.9 42.75,48.9 43.95,45.2 44.1,42.6 55.7,46.8 133.4,74.8 133.6,57.55 124.6,44.65 133.25,117.2 128.85,122.2 128.9,118.55 129.85,89.2 120.25,30.5 133.35,34.25 133.4,22.9 105.85,37.25 108.7,38.45 111.45,39.25 115.85,45.5 100.4,50.45 103.5,50.05 46.35,20.9 43.85,21.8 43.95,16.95 51.4,18.95 44.65,28.95 46.95,32.15 44.35,32.5 47.05,36.1 44,36.05 52.75,43.25 49.65,26.95 49.65,33.45 49.1,22.5 50.15,16.4 58.8,46.95 61.6,47 52.4,36.45 57.75,38.3 55.35,35.95 64,41.35 63.75,29.2 63.45,37.3 124.45,83.75 120.6,88.05 120.45,92 95.1,114.45 99.45,114.4 98.6,121.7 107.15,127 112.1,118.35 112.15,113.35 115.85,117.3 120.45,127 95.65,126.9 68.55,97 74.4,82.05 72.7,78.55 67.25,78.5 75.4,58.95 70.9,58.95 66,58.9 60.9,58.75 58.45,56.15 55.7,53.9 84.05,67.4 85.75,60 84.15,71.9 84.15,69.6 89.1,65.5 79.1,72.05 79.45,68.3 52.45,97.55 52.45,85.5 64.35,73.4 52.5,79.55 53.3,74.75 39.05,71.3 32.7,63.65 18.5,69.25 23.9,108.15 52.65,16.3 55.25,16.3 81.15,19.7 87.15,19.65 92.9,19.7 96,19.75 55,97.55 57.55,97.55 60.1,97.45 49.95,97.55 47.4,97.55 44.8,97.55 42.35,97.5 39.9,97.5 37.3,97.55 34.65,97.55 32.15,97.55 29.6,97.55 27.1,97.5 24.5,97.45 24.5,89.45 27.1,88.2 29.7,86.8 32.2,85.5 34.8,84.1 37.45,82.55 39.95,81.4 42.4,80.2 44.95,78.8 47.5,77.4 50,76.4 54.95,84.5 50.05,85.85 47.45,86.65 24.4,93.9 27.05,93.2 29.5,92.6 32.1,91.8 34.65,91.2 37.25,90.1 39.8,89.15 42.35,88.2 44.85,87.45 57.55,83.55 60.15,82.4 60.7,77.6 57.55,77.55 55.1,77.2 54.95,91.8 57.5,91.3 60.1,90.15 52.4,92.1 49.95,92.25 52.4,53.4 57.9,59.3 86.35,63.2 59.7,27.6
  pour Top (isolate 0.5): 63,106.5 65.5,109 65.6,109 68,106.6 73.1,106.6 73.7,107.2 83.3,107.2 arc90 84.8,108.7 84.8,110.9 86.6,112.7 86.6,127.4 132.4,127.4 arc-90 133.7,126.1 133.7,94.8 arc-90 132.5,93.6 131.9,93.6 arc90 130.3,92 130.3,83.1 arc90 132.4,81 132.7,81 134.3,80.15 134,35.25 134,18.4 arc-90 130.7,16 43.9,16 arc-90 40,19.9 40,41.9 arc90 38.6,43.3 37.5,43.3 arc-90 36.8,44 36.8,44.6 arc90 34,47.4 16.2,47.4 arc-90 14.3,49.3 14.3,110.1 arc-90 17.2,113 29.9,113 arc90 31.2,114.3 31.2,118.1 arc90 29.5,119.8 29.5,119.9 30,119.9 arc90 31.4,121.3 31.4,125 arc-90 33.8,127.4 52.8,127.4 52.8,126.85 52.85,126.8 50.8,126.8 arc90 48.95,124.95 48.95,112.6 arc90 53.65,107.85 60.6,107.85 61.95,106.5
  pour Top (isolate 0.5): 83.65,245.3 39.25,245.25 39.55,230.6 41.15,230.6 42.7,229.05 43.75,229.05 45.25,230.55 46.6,230.55 48.5,228.65 48.5,229 50,230.5 51.6,230.5 52.55,229.55 52.55,226.6 51.95,226 49.95,226 48.5,227.45 48.4,227.45 46.95,226 44.85,226 43.55,227.3 43.05,227.3 41.75,226 39.65,226 38.4,227.25 36.85,225.7 27.65,225.7 arc-90 26.5,226.85 26.5,231.9 arc-90 28,233.4 37.95,233.65 38.3,245.3 17.25,245.3 arc90 13.05,241.1 13.05,210.3 arc90 15.95,207.4 34.65,207.4 arc90 36.55,209.3 36.55,211.4 arc-90 38.65,214.7 85.05,214.7 arc90 86.65,216.3 86.65,242.3 arc90
  pour Bottom (isolate 0.5): 86.85,216.6 86.85,242.3 arc90 83.75,245.4 17.45,245.4 arc90 12.85,240.8 12.85,210.6 arc90 16.05,207.4 35.4,207.4 arc90 37.7,209.7 37.7,218.9 arc90 36.7,219.9 19.75,219.9 arc-90 18.95,220.7 18.95,232.7 arc-90 19.85,233.6 27,233.6 arc90 28.3,234.9 28.3,236.7 28.9,237.3 31.9,237.3 35.4,240.8 59.3,240.8 61.5,238.6 61.5,237.6 62,237.1 73.9,237.1 74.6,236.4 74.6,234.9 75.2,234.3 75.7,234.3 76.6,233.4 82.2,233.4 arc-90 83.9,231.7 83.9,230.3 arc90 84.4,229.8 84.7,229.8 arc-90 86.3,228.2 86.3,224 arc-90 83.2,220.9 82.4,220.9 arc-90 81,222.3 81,230.3 arc90 80.3,231 76.6,231 arc90 76.3,230.7 76.3,230.6 arc-90 75.7,230 74.4,230 arc90 73.9,229.5 73.9,224.9 arc90 76.5,222.3 76.9,222.3 arc-90 77.5,221.7 77.5,216.3 arc-90 76.5,215.3 74.9,215.3 73.3,216.9 72.8,216.9 71.1,215.2 69.2,215.2 67.3,217.1 66.9,217.1 65,215.2 63,215.2 62.1,216.1 62.1,217.9 64.4,220.2 70.2,220.2 arc90 71.2,221.2 71.2,229.8 arc90 70.3,230.7 69,230.7 arc-90 64.3,233.9 64.3,234.3 arc90 64.1,234.5 62.1,234.5 arc90 61.5,233.9 61.5,231.85 63,230.35 63,229.2 arc-90 61.35,227.55 61.3,227.55 arc-90 58.7,230.15 58.7,237.8 58,238.5 52.8,238.5 52.5,238.2 52.5,236.5 52.2,236.2 51,236.2 50.9,236.1 50.9,231.9 50.6,231.6 48.1,231.6 47.6,232.1 47.6,233.3 47.1,233.8 44.5,233.8 44.2,234.1 44.2,234.7 41.6,234.7 40.8,235.5 39,235.5 38.4,234.9 38.4,232.1 37.7,231.4 37.7,227.8 arc-90 35.7,225.7 22.3,225.7 arc90 21.7,225.1 21.7,223.6 arc90 22.2,223.1 37.1,223.1 arc90 38.8,224.8 39.7,230.6 41,230.6 43.2,228.4 43.2,228.5 45.2,230.5 46.6,230.5 48.3,228.8 50,230.5 51.6,230.5 52.6,229.5 52.6,224.2 58.4,218.4 58.4,215.4 arc90 59.2,214.6 84.75,214.6 arc90
  pour Bottom (isolate 0.5): 116.3,82 115.6,81.3 112.5,81.3 112.1,80.9 112.1,78.6 112.8,77.9 115,77.9 115,74.9 115.4,74.5 121.8,74.5 arc90 122.75,75.45 122.75,79.35 arc90 122,80.1 118.2,80.1 116.4,81.9 116.4,82.7 116.3,82.7
  pour Bottom (isolate 0.5): 134,102.6 134.05,94.85 arc-90 132.5,93.6 131.9,93.6 arc90 130.3,92 130.3,83.1 arc90 132.4,81 arc-90 133.9,79.5 133.9,19.3 arc-90 130.6,16 44.05,16 arc-90 40,20.05 40,41.7 arc90 38.3,43.4 37.85,43.4 37.05,44.2 37.05,44.55 arc90 34.2,47.4 16.25,47.4 arc-90 14.3,49.35 14.3,109.9 arc-90 17.4,113 47.7,113 arc-90 48.95,111.75 48.95,110.8 arc-90 48.1,109.95 29.35,109.95 arc90 27.2,107.8 81.1,107.8 arc90 86.65,113.35 86.65,125.95 arc-90 88.1,127.4 131.75,127.4 arc-90 133.7,125.45 134.65,102.65
  pour Bottom (isolate 0.5): 93.8,19.5 93,16.4 93.4,16 95.4,16 95.7,16.3 95.5,19 93.95,19.6
  pour Bottom (isolate 0.5): 58.9,19.8 60.5,19.8 60.8,19.5 60.8,16.2 60.6,16 58.8,16 58.5,16.3 58.5,19.4
  pour Bottom (isolate 0.5): 72,19.8 72.4,19.4 72.4,16.3 72.1,16 70.5,16 70.1,16.4 70.1,19.6 70.3,19.8
  pour Bottom (isolate 0.5): 81.5,19.6 83.8,19.6 84.2,19.2 84.2,16.4 83.8,16 81.4,16 81.2,16.2 81.2,19.3
  pour Bottom (isolate 0.406): 97.4,47.4 99.05,47.35 99.65,47.35 99.65,44.7 99.4,44.45 98,44.45 97.7,44.15 97.7,43.75 97.75,43.7 97.75,39.25 99.7,37.3 99.7,32.3 98.95,32.3 97.95,33.3 97.95,38 98,38.05 93.95,42.1 93.95,47.6 93.05,48.5 93.05,49.75 94.3,51 95.35,51 95.75,50.6 95.75,49.85 94.35,48.45 94.35,43.35 96.9,43.35 97.25,43.7 97.25,47.4
I1+
  Bottom 0.3: U1.14 84.53,47.33 78.6,41.4 73.3,41.4 71.85,39.95 C30.1
  Bottom 0.406: 74.1,36.6 74.1,38.1 73.35,38.85 71.85,38.85 C30.1 | 74.1,36.6 74.07,36.57 C17.1 | R17.1 74.04,36.54 74.1,36.6
I1-
  Bottom 0.3: U1.15 84.03,48.13 78.2,42.3 73,42.3 72.3,42.3 70.14,40.14 C30.2
  Bottom 0.406: R18.1 68.1,34.7 68.07,34.73 C18.2 68.07,38.07 68.87,38.87 C30.2
I2+
  Bottom 0.3: U1.12 85.53,45.73 83.6,43.8 83.6,38.8 83.68,38.72 | 83.68,38.72 83.7,38.7 | 83.68,38.72 C16.1
  Bottom 0.406: 83.7,38.7 85.1,38.7 85.7,38.1 85.7,36.8 C12.1 | C12.1 85.7,36.7 | 85.65,34.75 85.6,34.7 | 85.65,34.75 R14.2 | C12.1 85.7,36.75 85.7,34.8 85.65,34.75
I2-
  Bottom 0.3: U1.13 85.03,46.63 81.9,43.5 81.9,38.8 81.93,38.77 C16.2
  Bottom 0.406: C16.2 81.92,38.72 81.9,38.7 80.3,38.7 79.55,37.95 79.55,36.8 79.56,36.79 C15.2 79.56,34.8 79.65,34.8 79.91,34.81 79.9,34.8 R15.2
I3+
  Bottom 0.3: 93.75,38.95 93.75,40.1 91.9,41.95 88.4,41.95 86.53,43.82 U1.10 | 93.75,38.95 93.75,38.85 | 93.75,38.95 93.78,38.92 C11.1
  Bottom 0.406: R11.1 C9.1 95.84,38.01 94.9,38.95 93.85,38.95 93.85,38.94 C11.1
  Bottom 0.61: C9.1 95.84,36.84 95.85,36.85 | 93.85,38.95 C11.1
I3-
  Bottom 0.3: C11.2 92.15,38.95 92.15,40.65 91.55,41.25 88.15,41.25 86.03,43.37 U1.11 | C10.2 90.1,36.7 | C10.2 | 90.15,38.45 90.15,36.75 C10.2
  Bottom 0.406: C11.2 90.62,38.92 90.15,38.45 90.15,34.75
  Bottom 0.61: 90.15,34.75 90.14,34.74 R12.1
IN+
  Bottom 0.3: U1.16 83.53,48.93 79.2,44.6 65.6,44.6 60.6,39.6 | C34.1 60.63,36.9 60.6,36.9 60.6,39.6 | 60.6,39.6 60.8,39.8
  Bottom 0.406: 62.7,34.9 62.68,34.9 C31.1 62.68,34.92 62.7,34.9 | R20.2 62.7,32.93 62.7,34.9 | 62.7,34.9 62.7,36.25 62.03,36.92 C34.1
IN-
  Bottom 0.3: U1.17 83.03,49.63 78.8,45.4 64.6,45.4 59.2,40 59,39.8 59,36.9 58.97,36.9 C34.2
  Bottom 0.406: R21.2 56.6,32.7 56.6,34.74 C33.2 56.78,36.28 57.4,36.9 58.9,36.9 58.92,36.92 C34.2
LED1  (via drill 0.5 pad 0.9)
  Top 0.3: v88.3,96.8 88.73,97.23 94.13,97.23 95.2,98.3 95.3,98.3 | 95.3,98.3 101.3,98.3 102.67,96.93 LED1.K | JP15.5 95.3,99.48 95.3,98.3
  Bottom 0.3: U1.62 84.53,79.27 80.6,83.2 80.6,91.2 86.2,96.8 v88.3,96.8
LED2  (via drill 0.5)  (2 unrouted)
  Top 0.3: v88.3,98.1 93.4,98.1 93.8,98.5 93.8,100.4 95.1,101.7 95.1,102.7 96.1,103.7 101.8,103.7 102.6,102.9 | LED2.K 102.61,102.89
  Bottom 0.3: U1.61 84.03,78.87 80,82.9 80,91.9 86.2,98.1 v88.3,98.1
LED3  (via drill 0.5 pad 0.9)
  Top 0.3: LED3.K 101.57,104.4 95,104.4 93.75,103.15 93.75,102.15 93.75,101.5 92.5,100.25 92.5,99.75 92.55,99.7 | 92.55,99.7 92.6,99.7 92.3,99.4 v88.3,99.4 | 92.55,99.7 JP15.7
  Bottom 0.3: v88.3,99.4 86.3,99.4 79.3,92.4 79.3,82.7 83.53,78.47 U1.60
LINE-VA
  Bottom 0.3: 90.1,202.2 90.12,202.18
  Bottom 0.406: 80.35,209.15 80.35,209.1 80.28,209.17
  Bottom 1.016: 88.6,202.2 88.7,202.1 | 88.6,202.2 81.65,209.15 80.35,209.15 | 90.2,202.2 90.1,202.2 | 90.2,202.2 95.9,202.2 | 95.9,202.2 L1.2 | TR1.1 121.76,203.49 arc90 121.75,203.5 arc-90 117.85,199.6 98.55,199.6 95.95,202.2 95.9,202.2 | R38.1 80.28,209.17 | 90.12,202.18 90.12,200.9 | 90.12,200.9 R4.1 | 91.38,202.18 90.18,200.92 90.2,200.9 90.15,200.9 | 88.62,202.18 89.88,200.98 90.15,200.9 | 88.6,202.2 90.2,202.2 | 90.12,200.9 90.15,200.9
LINE-VB  (via drill 1 pad 1.78)  (2 unrouted)
  Top 1.016: R5.1 67.25,199.62 67.25,199.6 64.05,202.8 v56.5,202.8
  Bottom 1.016: R5.1 67.2,199.65 arc-90 67.15,199.7 arc90 R5.1 70.54,199.64 73.05,202.15 | R39.1 50.63,209.1 50.6,209.1 50.6,208.7 56.45,202.85
LINE-VC  (1 unrouted)
  Bottom 0.3: R40.1 44.6,209.19 44.6,209.2 | R6.1 44.85,199.8 | R6.1 | 45.15,199.7 44.95,199.7 R6.1
  Bottom 1.016: 45.15,199.7 49,199.7 50.55,201.25 L3.2 | 50.6,202.25 50.6,203.15 44.65,209.1 44.6,209.2
N$1
  Top 1.016: 26.27,166.88 V-N.1 26.17,166.9 26.05,166.9
  Top 2.54: R1.1 98.19,168.04 93.55,163.4 73.15,163.4 | 51.05,163.4 29.75,163.4 26.27,166.88 | 51.05,163.4 73.15,163.4 | R3.1 51.05,172.6 51.05,163.4 | R2.1 73.15,172.19 73.15,163.4 | 26.05,193.4 L4.1 | 26.05,166.9 26.05,193.4 | 26.05,193.4 25.95,193.5
N$2
  Bottom 1.016: L3.1 arc90 50.45,192.1 arc-90 50.54,192.01 R3.2 50.52,184.53 arc-90 50.45,184.6 arc-90 57.41,177.64 V-C.MP
N$3
  Bottom 1.016: L2.1 arc-90 73.05,192.1 arc90 73,192.05 R2.2 73.03,184.48 arc90 73.05,184.5 arc-90 79.78,177.77 V-B.MP
N$4
  Bottom 1.016: L1.1 95.92,191.97 arc-90 95.95,192 arc90 95.91,191.96 R1.2 95.88,184.53 arc90 95.85,184.5 arc-90 102.64,177.71 V_A.MP
N$5
  Bottom 0.3: 20.45,231.55 20.46,231.55 D14.C
  Bottom 1.016: D14.C 20.45,231.55 JP2.2 D16.C
N$6
  Bottom 0.406: R12.2 92.29,34.81 C19.2 90.65,32.85 90.35,32.55 90.35,30.97 R8.1 90.4,30.95 R37.1
N$7
  Bottom 1.016: JP7.2 40.85,218.95 40.8,219 40.25,218.45 G1.+
N$8
  Bottom 1.016: R4.2 90.08,167.82 arc90 90.05,167.8 arc90 85.46,172.39 C1.1
N$9
  Bottom 1.016: R5.2 67.16,167.9 arc-90 67.15,167.9 arc90 62.54,172.51 C2.1
N$10
  Bottom 1.016: R6.2 44.9,167.95 arc-90 44.85,167.9 arc90 40.22,172.53 C3.1
N$11
  Bottom 1.016: C1.2 83.23,198.92 arc90 75.65,206.5 arc-90 75.66,206.51 D1.A 75.84,206.51 arc-90 75.85,206.5 arc-90 75.84,206.49 D4.C
N$12
  Bottom 1.016: D2.A 69.96,206.49 69.95,206.5 69.86,206.41 D5.C 67.13,204.18 60.45,197.5 60.45,195.1 60.44,195.1 C2.2
N$13
  Bottom 1.016: 61.45,206.5 61.43,206.48 D6.C 64.23,206.48 | 64.23,206.48 64.22,206.47 D3.A 64.15,206.49 | 64.23,206.48 64.25,206.5 | C3.2 54.58,195.13 64.15,204.7 64.15,206.49 | 64.15,206.49 64.15,206.5
N$14
  Bottom 0.3: D30.2 96.65,24.3 96.65,24.2
  Bottom 0.406: D8.A 97.5,21.3 | 97.54,18.06 arc90 97.6,18 arc-90 97.54,18.06 | D9.C 97.54,18.06 | 96.65,24.2 96.65,22.75 97.5,21.9 97.5,21.22 97.5,18.1 | 97.5,17.9 97.5,13.4 | 96.7,24.4 96.69,24.39 D30.2 96.7,26.9 R36.2
  Bottom 0.6: 97.5,21.22 D8.A | 97.5,18.1 D9.C | 97.5,13.4 LSP7.MP | 97.6,18 97.5,17.9
N$15
  Bottom 1.016: D36.C 92.85,219.51 92.85,222.5 D35.A 92.94,222.51 92.95,222.5 92.95,222.6 93.05,222.6 94.6,224.15 TR1.4
N$16
  Bottom 0.406: 91.6,21.1 91.6,23.66 D30.1 90.4,25.44 R37.2 90.4,27.3 | 91.6,21.09 91.6,18.01 | 91.6,17.97 91.6,13.4
  Bottom 0.6: 91.6,21.1 91.59,21.1 D10.A 91.6,21.09 | 91.6,18.01 D17.C 91.6,17.97 | 91.6,13.4 LSP8.MP
N$17
  Bottom 0.406: 85.2,24.45 85.19,24.44 D31.2 | 85.16,24.34 85.15,24.35 | D31.2 85.16,24.34 | 85.16,24.34 85.74,23.76 D18.A 85.74,18.14 arc-90 85.7,18.1 arc-90 85.74,18.06 D19.C 85.74,13.31 | 85.74,13.31 85.73,13.32 LSP9.MP | 85.74,13.31 85.8,13.25 | R56.2 85.3,24.45 D31.2
N$18
  Bottom 0.406: 79.9,17.94 79.9,13.41 | 79.9,21.33 79.9,18.04 | D20.A 79.88,23.58 D31.1 80.05,24.4 R57.2
  Bottom 0.6: 79.9,17.94 D21.C 79.9,18.04 | 79.9,13.41 LSP10.MP | 79.9,21.4 79.9,21.33 D20.A
N$19
  Bottom 0.406: 74,18 74,21.36 74,23.6 D32.2 74.05,24.57 R58.2 | 74.1,17.94 74.1,13.3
